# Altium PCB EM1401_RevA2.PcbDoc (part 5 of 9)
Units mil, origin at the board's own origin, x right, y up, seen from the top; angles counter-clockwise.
Board outline 7800 x 5300 mil, 6 copper layers (Top Layer, MidLayer1, MidLayer2, MidLayer3, MidLayer4, Bottom Layer), stack 16.8 mil thick; 751 components, 531 nets, 2554 pads, 1388 vias.
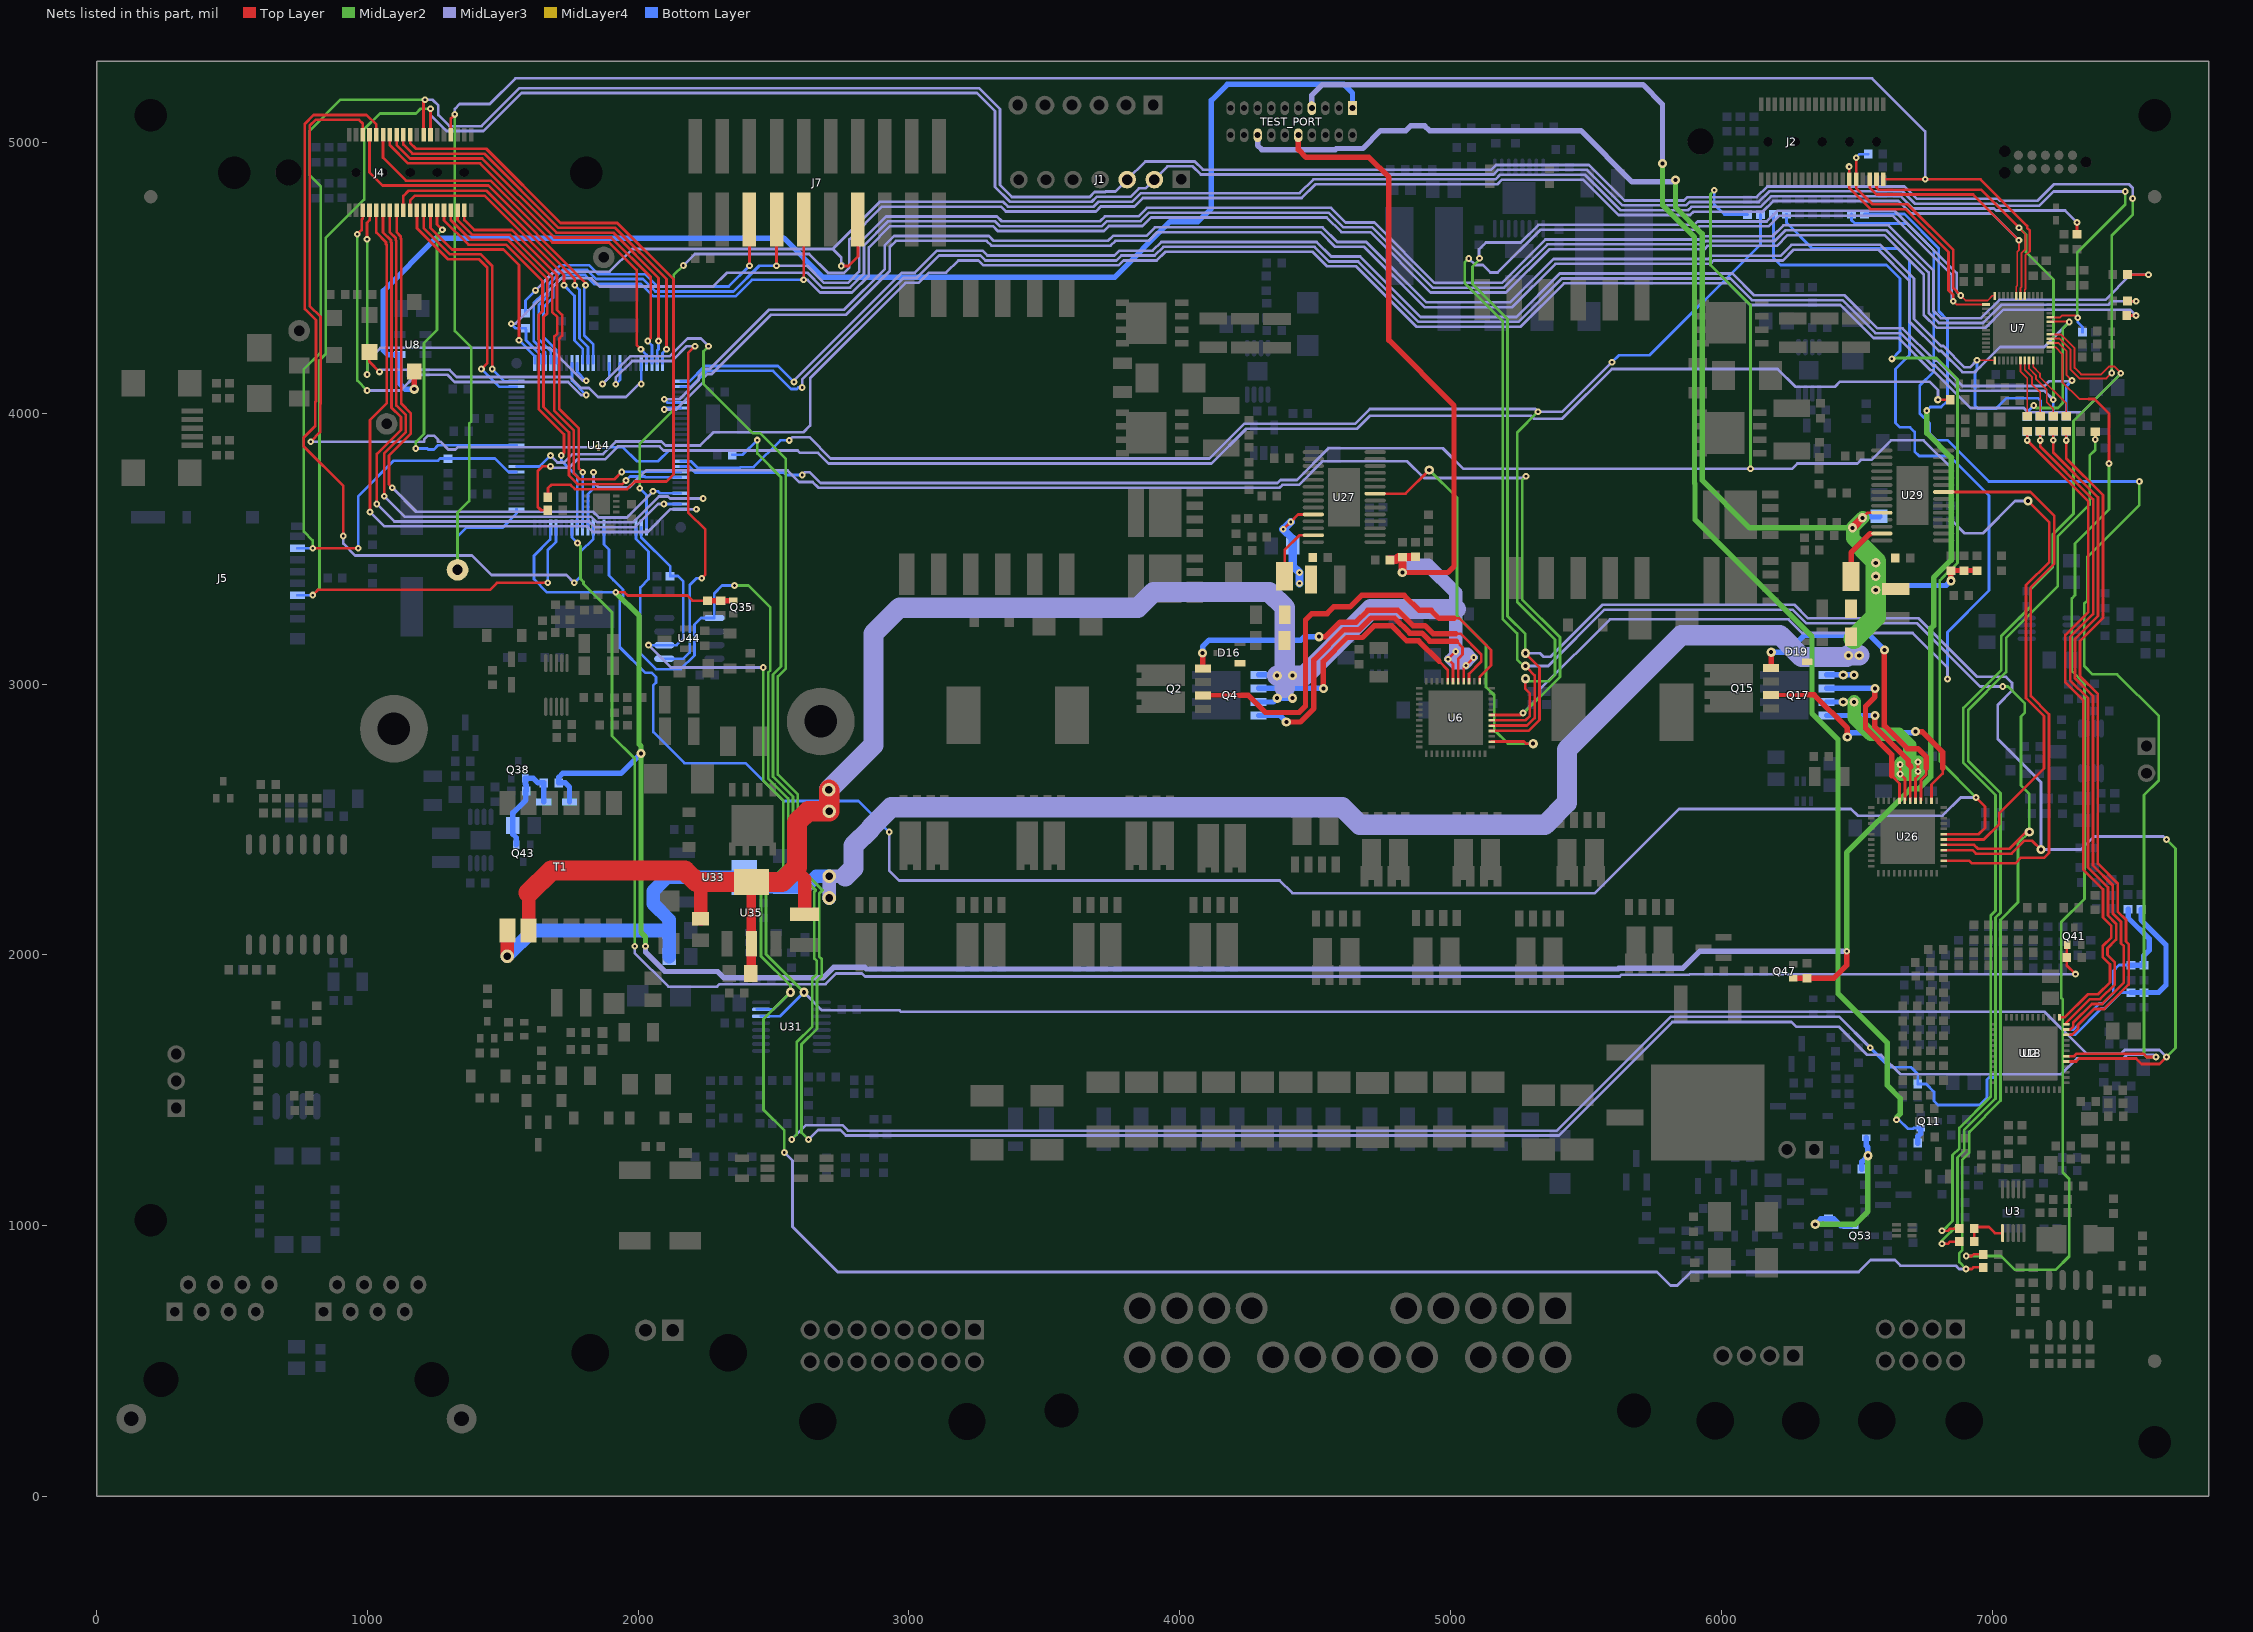
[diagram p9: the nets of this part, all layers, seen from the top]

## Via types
v1: diameter 25, hole 10, Top Layer to Bottom Layer, tented both sides, 275 vias
v2: diameter 16, hole 8, Top Layer to Bottom Layer, tented both sides, 240 vias
v3: diameter 34, hole 15, Top Layer to Bottom Layer, tented both sides, 158 vias
v4: diameter 34, hole 15, Top Layer to Bottom Layer, 154 vias
v5: diameter 34, hole 15, Top Layer to Bottom Layer, tented top, 95 vias
v6: diameter 34, hole 15, Top Layer to Bottom Layer, tented bottom, 89 vias
v7: diameter 25, hole 10, Top Layer to Bottom Layer, tented bottom, 75 vias
v8: diameter 25, hole 10, Top Layer to Bottom Layer, 62 vias
v9: diameter 28, hole 8, Top Layer to Bottom Layer, tented both sides, 60 vias
v10: diameter 24, hole 8, Top Layer to Bottom Layer, 53 vias
v11: diameter 25, hole 10, Top Layer to Bottom Layer, tented top, 28 vias
v12: diameter 50, hole 28, Top Layer to Bottom Layer, 28 vias
v13: diameter 25, hole 8, Top Layer to Bottom Layer, tented both sides, 18 vias
v14: diameter 50, hole 28, Top Layer to Bottom Layer, tented top, 12 vias
v15: diameter 25, hole 8, Top Layer to Bottom Layer, tented top, 9 vias
v16: diameter 20, hole 8, Top Layer to Bottom Layer, tented both sides, 9 vias
v17: diameter 24, hole 8, Top Layer to Bottom Layer, tented bottom, 4 vias
v18: diameter 24, hole 8, Top Layer to Bottom Layer, tented top, 4 vias
v19: diameter 28, hole 10, Top Layer to Bottom Layer, tented both sides, 3 vias
v20: diameter 35, hole 14, Top Layer to Bottom Layer, 3 vias
v21: diameter 50, hole 28, Top Layer to Bottom Layer, tented both sides, 2 vias
v22: diameter 50, hole 28, Top Layer to Bottom Layer, tented bottom, 2 vias
v23: diameter 30, hole 14, Top Layer to Bottom Layer, tented top, 2 vias
v24: diameter 28, hole 10, Top Layer to Bottom Layer, 1 vias
v25: diameter 35, hole 14, Top Layer to Bottom Layer, tented both sides, 1 vias
v26: diameter 35, hole 14, Top Layer to Bottom Layer, tented top, 1 vias

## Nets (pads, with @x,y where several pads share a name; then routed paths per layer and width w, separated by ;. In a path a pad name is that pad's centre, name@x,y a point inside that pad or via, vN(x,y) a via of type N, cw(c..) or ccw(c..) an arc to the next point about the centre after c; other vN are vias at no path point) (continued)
DOUT_LS: D56.1 Q53.2 R162.2 R263.1 | length 696.9
  MidLayer2 w20: v5(6347,1005) 6494,1005 6541.42,1052.42 v3(6541.42,1258.42)
  Bottom Layer w20: v5(6347,1005) 6367.56,1025.56 R263.1@6396,1025.56 6415.44,1025.56 6441,1000 Q53.2@6478,1000 ; R162.2@6518.98,1209 6518.98,1235.97 v3(6541.42,1258.42) 6541,1258.83 6541,1290 6535.42,1295.58 D56.1@6535.42,1324
EN_BOT: U6.26 U27.8 | length 1616.4
  Top Layer w10: U27.8@4721.62,3703.33 4833.74,3703.33 v5(4921.42,3791) ; U6.26@5152.77,2787.66 5271.09,2787.66 5278.75,2780 v4(5305.42,2780)
  MidLayer2 w10: v5(4921.42,3791) 5024,3688.42 5024,3252.33 5131.42,3144.91 5131.42,2988.75 5161.42,2958.75 5161.42,2831.04 5212.46,2780 v4(5305.42,2780)
EN_CEXT_BYPASS_: Q11.1 R24.1 TEST_PORT.7 | length 5673.1
  MidLayer2 w20: v4(5783,4923) 5783,4768.6 5901,4650.6 5901,3741.4 5903,3739.4 5903,3607 6335,3175 6335,2892 6431,2796 6431,1857 6613,1675 6613,1518 6660.5,1470.5 6660.5,1412.37 6647,1398.87 v1(6647,1391)
  MidLayer3 w20: TEST_PORT.7@4488,5127 4488,5175 4527,5214 5710,5214 5783,5141 v4(5783,4923) v4@5782,4922
  Bottom Layer w10: v1(6647,1391) 6656,1391 6689,1358 6707.48,1358 6709.89,1360.41 Q11.1@6736.01,1360.41
  Bottom Layer w20: R24.1@6726,1305 6726,1330 6736,1340 Q11.1@6736.01,1360.41
EN_CHECKSUM_: Q41.1 R137.2 U14.43 | length 7191
  Top Layer w10: Q41.1@7277.83,2037.01 7275.86,2035.04 R137.2@7275.86,1991 7275.86,1961.14 v1(7308,1929)
  MidLayer2 w10: v1(1776,3521) 1787,3510 1787,3389 1798.5,3377.5 1798.5,3370.44 1903.5,3265.44 1903.5,2808.49 1987.42,2724.57 v7@1987.42,2032
  MidLayer3 w10: v7(1987,2032) 1987,2007 2111.5,1882.5 2291.56,1882.5 2301.06,1892 2692,1892 2731,1931 2827,1931 2838,1920 5624.47,1920 5631.47,1927 5882,1927 5884,1929 v1(7308,1929)
  Bottom Layer w10: U14.43@1755.57,3578.85 1755.57,3541.43 v1(1776,3521)
EN_SW_: C104.2 D21.1 Q35.1 Q47.1 R87.2 R138.2 R169.1 R244.1 U14.47 | length 10817.1
  Top Layer w10: v1(1917,3339) 1949.94,3339 1961.44,3327.5 2181.5,3327.5 2201,3308 C104.2@2256,3308
  Top Layer w20: C104.2@2256,3308 2304.44,3308 R244.1@2305,3308.56 Q35.1@2350.5,3308.59 ; Q47.1@6265.91,1914.41 6316.01,1914.41 R169.1@6316.42,1914 6416,1914 6463,1961 v1(6463,2013)
  MidLayer2 w20: v1(1917,3339) 2003,3253 2003,2778 2010.42,2770.58 v4(2010.42,2744) 2010.42,2082.58 2027,2066 v7(2027,2032) ; v1(6463,2013) 6463,2378 6698,2613 6729,2613 6774,2658 6774,3206 6784,3216 6784,3393 6849,3458 6849,3837 6759,3927 v8(6759,4010)
  MidLayer3 w20: v7(2027,2032) 2027,2010 2098.5,1938.5 2293.63,1938.5 2317.13,1915 2682.47,1915 2721.47,1954 2836.53,1954 2842.53,1948 5619.95,1948 5621.95,1950 5857,1950 5920,2013 v1(6463,2013)
  Bottom Layer w10: U14.47@1676.83,3578.85 1675.15,3577.17 1675.15,3534.15 1615,3474 1615,3387.54 1663.54,3339 v1(1917,3339) ; R87.2@6529,4735.88 6676.12,4735.88 6803,4609 6803,4377 6835,4345 6835,4046 6812,4023 6772,4023 v8(6759,4010)
  Bottom Layer w20: D21.1@1746.49,2565 1746.49,2619.51 1731,2635 R138.2@1707,2635 1707,2656 1721,2670 1936.42,2670 v4(2010.42,2744)
EN_TOP: U26.26 U29.8 | length 2162.2
  Top Layer w10: U29.8@6821.05,3709.47 7141.95,3709.47 7229.42,3622.01 7229.42,3444.09 7143.14,3357.81 7143.14,2955.72 7210.42,2888.44 7210.42,2376.57 7192.84,2359 7107.37,2359 7086.37,2338 6925.5,2338 6916.09,2347.42 U26.26@6821.77,2347.42
EPIOS0/A0/D0: J4.5 U14.83 | length 1691.4
  Top Layer w10: v11(963,4661) 979,4677 979,4715 983,4719 J4.5@983,4750
  MidLayer2 w10: v11(963,4661) 963,4120.5 v1(999,4084.5)
  MidLayer3 w10: v1(999,4084.5) 1122.5,4084.5 1180.5,4142.5 1295.86,4142.5 1322.36,4116 1741.53,4116 1789.53,4068 v7(1808,4068)
  Bottom Layer w10: U14.83@1755.57,4185.15 1755.57,4120.43 v7(1808,4068)
EPIOS1/A1/D1: J4.7 U14.84 | length 1620.1
  Top Layer w10: v8(998.5,4643) 998.5,4703.5 1008.5,4713.5 1008.5,4749.5 J4.7@1008,4750
  MidLayer2 w10: v8(998.5,4643) 999,4642.5 v1(999,4143)
  MidLayer3 w10: v1(999,4143) 999,4193 1048,4242 1674,4242 1796,4120 v7(1808,4120)
  Bottom Layer w10: U14.84@1775.26,4185.15 1775.26,4152.74 v7(1808,4120)
EPIOS2/A2/D2: J4.9 U14.25 | length 2484.9
  Top Layer w10: v7(1009.5,3635.5) 1009.5,3975.5 1071,4037 1071,4622.18 1069,4624.18 1069,4631.63 1033,4667.63 J4.9@1033,4750
  MidLayer3 w10: v7(1009.5,3635.5) 1062.5,3582.5 1811.46,3582.5 1832.52,3561.44 2035.44,3561.44 2120,3646 v1(2215,3646)
  Bottom Layer w10: U14.25@2157.15,3645.78 2214.78,3645.78 v1(2215,3646)
EPIOS3/A3/D3: J4.11 U14.24 | length 2342.4
  Top Layer w10: v7(1035,3665) 1035,3849.94 1124,3938.94 1124,3985.6 1089,4020.6 1089,4629.63 1087,4631.63 1087,4639.09 1058,4668.09 J4.11@1058,4750
  MidLayer3 w10: v7(1035,3665) 1099.5,3600.5 1818.92,3600.5 1839.98,3579.44 1988.44,3579.44 2074,3665 v1(2095,3665)
  Bottom Layer w10: v1(2095,3665) 2156.68,3665 U14.24@2157.15,3665.46
EPIOS4/A4/D4: J4.13 U14.23 | length 2457
  Top Layer w10: v7(1062,3694) 1062,3851.48 1142,3931.48 1142,3993.06 1107,4028.06 1107,4637.09 1105,4639.09 1105,4646.54 1083,4668.54 J4.13@1083,4750
  MidLayer3 w10: v7(1062,3694) 1137.5,3618.5 1826.37,3618.5 1847.43,3597.44 1980.99,3597.44 2076.54,3693 2110,3693 2117.85,3685.15 v1(2239.85,3685.15)
  Bottom Layer w10: U14.23@2157.15,3685.15 v1(2239.85,3685.15)
EPIOS5/A5/D5: J4.15 U14.22 | length 2238.1
  Top Layer w10: v7(1092,3725) 1080,3737 1080,3844.03 1160,3924.03 1160,4000.51 1125,4035.51 1125,4644.54 1123,4646.54 1123,4654 1108,4669 J4.15@1108,4750
  MidLayer3 w10: v7(1092,3725) 1180.5,3636.5 1833.83,3636.5 1854.89,3615.44 1958.44,3615.44 v1(2055,3712)
  Bottom Layer w10: v1(2055,3712) 2074,3712 2081.17,3704.83 U14.22@2157.15,3704.83
EPIOS6/A6/D6: J4.17 U14.86 | length 1159.9
  Top Layer w10: J4.17@1133,4750 1133,4802.46 1152.54,4822 1440.54,4822 1766,4496.54 v1(1766,4473)
  Bottom Layer w10: v1(1766,4473) 1783,4456 1783,4276 1814.63,4244.37 U14.86@1814.63,4185.15
EPIOS7/A7/D7: J4.19 U14.85 | length 1087.7
  Top Layer w10: J4.19@1158,4750 1158,4786 1176,4804 1433.09,4804 1726,4511.09 v1(1726,4473)
  Bottom Layer w10: v1@1726.46,4473 v1(1726,4473) 1765,4434 1765,4268.54 1794.94,4238.6 U14.85@1794.94,4185.15
EPIOS8/A8/D8: J4.21 U14.74 | length 926.6
  Top Layer w10: J4.21@1183,4750 1183,4683.54 1297.54,4569 1411.54,4569 1443,4537.54 1443,4186 v7(1421,4164)
  Bottom Layer w10: v7(1421,4164) 1486.46,4098.54 U14.74@1550.85,4098.54
EPIOS9/A9/D9: J4.23 U14.75 | length 866.4
  Top Layer w10: J4.23@1208,4750 1208,4684 1305,4587 1419,4587 1461,4545 v7(1461,4164)
  Bottom Layer w10: v7(1461,4164) 1506.78,4118.22 U14.75@1550.85,4118.22
EPIOS10/A10/D10: J4.25 U14.76 | length 835.5
  Top Layer w10: J4.25@1233,4750 1233,4685 1313,4605 1503,4605 1560,4548 v8(1560,4270)
  Bottom Layer w10: v8(1560,4270) 1617.78,4212.22 U14.76@1617.78,4185.15
EPIOS11/A11/D11: J4.27 U14.63 | length 1309
  Top Layer w10: J4.27@1258,4750 1257,4749 1257,4698 v8(1277,4678)
  MidLayer2 w10: v7(1179,3870) 1179,3894 1209,3924 1209,4260 1257,4308 1257,4658 v8(1277,4678)
  Bottom Layer w10: v7(1179,3870) 1220.94,3870 1224.44,3866.5 1245.56,3866.5 1261.06,3882 U14.63@1550.85,3882
EPIOS12/A12/D12: J4.29 U14.42 | length 1476.7
  Top Layer w10: J4.29@1283,4750 1283,4712.63 1372.63,4623 1511.63,4623 1646.5,4488.13 1646.5,4377.02 1632.5,4363.02 1632.5,4016.13 1726.39,3922.25 1726.39,3854.39 v7(1716,3844)
  Bottom Layer w10: v7(1716,3844) 1716,3824.94 1775.26,3765.68 U14.42@1775.26,3578.85
EPIOS13/A13/D13: J4.31 U14.19 | length 1692.2
  Top Layer w10: J4.31@1308,4750 1308,4713.09 1380.09,4641 1519.09,4641 1664.5,4495.59 1664.5,4369.56 1650.5,4355.56 1650.5,4023.59 1744.39,3929.7 1744.39,3770.16 1776.04,3738.5 1941.5,3738.5 v1(1955,3752)
  Bottom Layer w10: v1(1955,3752) 1969.5,3766.5 2024.02,3766.5 2026.63,3763.89 U14.19@2157.15,3763.89
EPIOS14/A14/D14: J4.33 U14.18 | length 1660.3
  Top Layer w10: J4.33@1333,4750 1333,4713.54 1387.54,4659 1526.54,4659 1682.5,4503.04 1682.5,4374.56 1701.5,4355.56 1701.5,4294.44 1690.5,4283.44 1690.5,4009.04 1762.39,3937.16 1762.39,3777.61 1783.5,3756.5 1911.93,3756.5 v1(1939,3783.57)
  Bottom Layer w10: v1@1935,3783.57 1935.93,3784.5 2156.22,3784.5 U14.18@2157.15,3783.57
EPIOS15/A15/D15: J4.35 U14.41 | length 1442.7
  Top Layer w10: J4.35@1358,4750 1358,4714 1395,4677 1534,4677 1700.5,4510.5 1700.5,4382.02 1719.5,4363.02 1719.5,4286.98 1708.5,4275.98 1708.5,4016.5 1781,3944 1781,3796 v1(1795,3782)
  Bottom Layer w10: U14.41@1794.94,3578.85 1795,3578.91 v1(1795,3782)
EPIOS16/DQML: J4.6 U14.14 | length 2896.8
  Top Layer w10: v8@791,3896 825.5,3930.5 825.5,4034.56 828,4037.06 828,4355 787,4396 787,5062 809,5084 969,5084 983,5070 J4.6@983,5028
  MidLayer3 w10: v8@791,3895.5 1209.5,3895.5 1209.5,3902.56 1224.44,3917.5 1245.56,3917.5 1260.5,3902.56 1260.5,3895.5 1269.56,3895.5 1298.56,3866.5 1325.56,3866.5 1333.56,3874.5 v7(1853.5,3874.5)
  Bottom Layer w10: v7(1853.5,3874.5) 1944.56,3874.5 1996.06,3823 2074,3823 2113.32,3862.31 U14.14@2157.15,3862.31
  other v8: 791,3895
EPIOS17/DQMH: J4.8 U14.87 | length 1425.5
  Top Layer w10: J4.8@1008,5028 1008,4889 1056,4841 1447,4841 1806,4482 v1(1806,4473)
  Bottom Layer w10: v1@1809,4479 1806,4476 v1(1806,4473) 1801,4468 1801,4288 1834.32,4254.69 U14.87@1834.32,4185.15
EPIOS18/CASN: J4.10 U14.39 | length 3124
  Top Layer w10: v8(911,3547) 911,3731 765,3877 765,3910 807.5,3952.5 807.5,4042.5 810,4045 810,4344 769,4385 769,5069.46 801.54,5102 997,5102 1033,5066 J4.10@1033,5028
  MidLayer3 w10: v8(911,3547) 911,3519 955,3475 1386,3475 1458.21,3402.79 1735.21,3402.79 v1(1764,3374)
  Bottom Layer w10: v1(1764,3374) 1787.5,3397.5 1787.5,3489.41 1834.32,3536.23 U14.39@1834.32,3578.85
EPIOS19/RASN: J4.12 U14.97 | length 1551.7
  Top Layer w10: J4.12@1058,5028 1058,4944 1143,4859 1455.18,4859 1683.18,4631 1893,4631 1994.5,4529.5 1994.5,4252.5 v7(2010,4237)
  Bottom Layer w10: v7(2010,4237) 2031.17,4215.83 U14.97@2031.17,4185.15
EPIOS28/WEN: J4.14 U14.98 | length 1532.8
  Top Layer w10: J4.14@1083,5028 1083,4990 1150,4923 1416.63,4923 1690.63,4649 1900.46,4649 2047,4502.46 2047,4279 v7(2035,4267)
  Bottom Layer w10: v7(2035,4267) 2050.85,4251.15 U14.98@2050.85,4185.15
EPIOS29/CSN: J4.16 U14.99 | length 1524
  Top Layer w10: J4.16@1108,5028 1108,4991 1158,4941 1424.09,4941 1698.09,4667 1907.91,4667 2075,4499.91 v7(2075,4267)
  Bottom Layer w10: U14.99@2070.54,4185.15 2070.54,4232.54 2075,4237 v7(2075,4267)
EPIOS30/CKE: J4.18 U14.100 | length 1529.5
  Top Layer w10: J4.18@1133,5028 1133,4993 1167,4959 1431.54,4959 1705.54,4685 1915.37,4685 2105,4495.37 v7(2105,4237)
  Bottom Layer w10: U14.100@2090.22,4185.15 2090.22,4222.22 v7(2105,4237)
EPIOS31/CLK: J4.20 R286.1 | length 2462.7
  Top Layer w10: J4.20@1158,5028 1158,4999 1180,4977 1439,4977 1713,4703 1922.82,4703 2130.5,4495.32 2130.5,3774.5 2104.5,3748.5 1987.56,3748.5 1959.06,3720 1766,3720 1750,3736 1679,3736 1666.88,3723.88 R286.1@1666.88,3690
FAULT_INT_BOT_: R267.2 U6.31 U14.40 | length 9181.8
  Top Layer w10: U6.31@5152.77,2886.09 5259.5,2886.09 v1@5267.42,2894
  MidLayer2 w10: v1(5267.42,2893) 5270.46,2893 5404,3026.54 5404,3173 5264.42,3312.58 5264.42,3753.42 v11(5279,3768)
  MidLayer3 w10: v1(1835,3782) 1835,3746 1854.5,3726.5 1965.56,3726.5 1966.06,3727 1967,3727 2029.5,3789.5 2551.5,3789.5 2594.5,3746.5 2644.22,3746.5 2665.72,3725 4368.3,3725 4379.3,3736 4441,3736 4528,3823 4840,3823 4902,3761 5272,3761 v11(5279,3768) ; v1(5267.42,2893) 5331,2956.58 5331,2981.54 5588.46,3239 6248.54,3239 6298.54,3189 6706.84,3189 6835,3060.84 v8(6835,3019)
  Bottom Layer w10: U14.40@1814.63,3578.85 1814.63,3701.63 1835,3722 v1(1835,3782) ; R267.2@6241,4734.88 6241,4704 6336,4609 6650.27,4609 6695,4564.27 6695,4215.46 6643,4163.46 6643,3965 6660,3948 6697,3948 6714,3931 6714,3859 6731,3842 6843,3842 6988.92,3696.08 6988.92,3345.37 6835,3191.46 v8(6835,3019)
FAULT_INT_TOP_: R258.2 U14.37 U26.31 | length 9401.1
  Top Layer w10: U26.31@6821.77,2445.84 6822.12,2445.5 6920.56,2445.5 6920.9,2445.84 6929.1,2445.84 6929.44,2445.5 6950.56,2445.5 6974,2468.94 6974,2548 v7(6941,2581)
  MidLayer2 w10: v8@6633,4204 6794,4204 6872,4126 6872,3448 6835.5,3411.5 6817.92,3393.93 ; 6817.92,3393.92 6807,3383 6807,2715 v7(6941,2581)
  MidLayer3 w10: v8(2927,2454) 2927,2311 2963,2275 4369,2275 4416,2228 5533,2228 5844,2539 6479,2539 6504,2514 6817.35,2514 6884.35,2581 v7(6941,2581)
  Bottom Layer w10: U14.37@1873.68,3578.85 1873.68,3515.31 1892,3497 1892,3400.94 1908.44,3384.5 1908.5,3384.5 1944,3349 1944,3323 1932,3311 1932,3136 2026.5,3041.5 2050.56,3041.5 2065.5,3026.56 2065.5,3005.44 2056,2995.94 2056,2823 2171,2708 2397,2708 2537,2568 2813,2568 v8(2927,2454) ; R258.2@6193,4734.88 6193,4574 6219,4548 6610,4548 6660,4498 6660,4231 v8(6630,4201)
FPGA_CLK_: R85.2 R88.1 | length 5695.8
  Top Layer w10: R88.1@1666.88,3642 1642,3642 1629,3655 1629,3786 1647,3804 v7(1676,3804) ; v24(6800,4050) R85.2@6844.88,4050
  MidLayer3 w10: v7(1676,3804) 1681,3799 1744,3799 1775,3830 1877,3830 1925,3878 2079,3878 2094,3863 2588.94,3863 2597.94,3854 2664,3854 2703,3815 4117.62,3815 4245.62,3943 4655,3943 4703,3991 5297,3991 5308,3980 5412.46,3980 5595.96,4163.5 6208.04,4163.5 6273.54,4098 6419.57,4098 6438.57,4117 6769,4117 6800,4086 v24(6800,4050)
FPGA_MUX0: R92.1 U7.7 | length 206.8
  Top Layer w7: U7.7@7104.87,4195.91 7104.87,4155.27 7130,4130.15 R92.1@7130,3999.56
FPGA_MUX1: R97.1 U7.8 | length 231.1
  Top Layer w7: U7.8@7120.62,4195.91 7120.62,4160.74 7147,4134.36 7147,4108 7178,4077 R97.1@7178,3988.56
FPGA_MUX2: R99.1 U7.9 | length 244.5
  Top Layer w7: U7.9@7136.37,4195.91 7136.37,4166.2 7162,4140.57 7162,4127.85 7202,4087.85 7202,4040 7226,4016 R99.1@7226,3988.56
FPGA_MUX3: R101.1 U7.10 | length 257.8
  Top Layer w7: U7.10@7152.12,4195.91 7152.12,4171.67 7177,4146.79 7177,4134.06 7274,4037.06 R101.1@7274,3988.56
GATE_8B: Q4.2 U6.44 | length 962.7
  Top Layer w10: 4957.42,3085 4989.39,3053.03 U6.44@4989.39,3010.1
  Top Layer w20: v4(4530.42,2984) 4530.42,3084 4618.42,3172 4674.42,3172 4718.42,3216 4782.43,3216 4838.43,3160 4882.42,3160 4957.42,3085
  Bottom Layer w20: Q4.2@4291.75,2984 v4(4530.42,2984)
GATE_8T: Q17.2 U26.44 | length 659.5
  Top Layer w10: 6629.42,2662 6658.39,2633.03 U26.44@6658.39,2569.86
  Top Layer w20: v4(6567.42,2984) 6567.42,2953 6532.42,2918 6532.42,2837 6629.42,2740 6629.42,2662
  Bottom Layer w20: Q17.2@6388.75,2984 v4(6567.42,2984)
GATE_9B: Q4.4 U6.42 | length 1204
  Top Layer w10: 5022.06,3158.35 5044.5,3135.92 5044.5,3109.36 5028.76,3093.62 U6.42@5028.76,3010.1
  Top Layer w20: v4(4393.75,2860) 4445.42,2860 4495.42,2910 4495.42,3089.44 4606.98,3201 4663.42,3201 4706.42,3244 4794.02,3244 4850.02,3188 4894.01,3188 4923.66,3158.35 5022.06,3158.35
  Bottom Layer w20: Q4.4@4291.75,2884 4369.75,2884 v4(4393.75,2860)
GATE_9T: Q17.4 U26.42 | length 549
  Top Layer w10: U26.42@6697.76,2569.86 6697.76,2692.34 6700.42,2695
  Top Layer w20: v4(6567.42,2884) 6567.42,2841.6 6690.92,2718.1 6690.92,2704.5 6700.42,2695
  Bottom Layer w20: Q17.4@6388.75,2884 v4(6567.42,2884)
GATE_10B: Q2.4 U6.40 | length 1351.8
  Top Layer w10: 5020.42,3186.35 5037.06,3186.35 5113.42,3110 5113.42,3083.37 5068.13,3038.08 U6.40@5068.13,3010.1
  Top Layer w20: v5(4084.42,3115) 4084.42,3059.33 Q2.4@4085.75,3058 ; v4(4514.42,3175) 4538.42,3175 4592.42,3229 4651.82,3229 4694.82,3272 4805.62,3272 4861.62,3216 4905.61,3216 4935.26,3186.35 5020.42,3186.35
  Bottom Layer w20: v5@4084.42,3114 v5(4084.42,3115) 4084.42,3138 4108.42,3162 4447,3162 4460,3175 v4(4514.42,3175)
GATE_10T: Q15.4 U26.40 | length 1176.3
  Top Layer w10: U26.40@6737.13,2569.86 6737.13,2645.71 6757.42,2666 6757.42,2689
  Top Layer w20: Q15.4@6184.27,3059.24 6184.27,3117.71 v5@6184.42,3117.86 ; v4(6602.42,3126) 6602.42,2846.4 6687.32,2761.5 6725.92,2761.5 6757.42,2730 6757.42,2689
  Bottom Layer w20: v5(6184.27,3117.86) 6243.67,3117.86 6305.82,3180 6548.42,3180 v4(6602.42,3126)
GATE_11B: Q2.2 U6.38 | length 1673
  Top Layer w10: 5014.42,3243 5032.42,3243 5149.42,3126 5149.42,3068.46 5107.5,3026.54 U6.38@5107.5,3010.1
  Top Layer w16: Q2.2@4085.75,2959 4222.42,2959
  Top Layer w20: 4222.42,2959 4252.42,2959 4316.42,2895 4440.82,2895 4464.42,2918.6 4464.42,3237 4487.92,3260.5 4544.12,3260.5 4568.62,3285 4628.62,3285 4671.62,3328 4828.82,3328 4884.82,3272 4928.81,3272 4957.81,3243 5014.42,3243
GATE_11T: Q15.2 U26.38 | length 952
  Top Layer w10: U26.38@6776.5,2569.86 6776.5,2629.08 6817.42,2670 6817.42,2689
  Top Layer w16: Q15.2@6184.27,2959.24 6184.87,2959.83 6321.17,2959.83
  Top Layer w20: 6321.17,2959.9 6342.52,2959.9 6465.42,2837 v4(6465.42,2805) ; v4(6716.79,2824.62) 6741.99,2824.62 6817.42,2749.2 6817.42,2689
  Bottom Layer w20: v4(6465.42,2805) 6480.42,2820 6712.17,2820 v4(6716.79,2824.62)
GNDF1: C121.2 C126.2 C127.2 C164.2 C165.2 C215.1 C217.2 C219.2 C232.1 D16.1 Q4.1 Q4.3 R174.2 R220.1 R236.2 T1.8 TEST_PORT.10 U6.41 U6.43 U27.24 U27.27 U35.2 U35.4 | length 9866.2
  Top Layer w10: v11(4382,3572) 4383,3572 v11(4410,3599) 4437.56,3626.56 U27.24@4493.28,3626.56 ; R174.2@4387.4,3398 4387.4,3495.4 4441.78,3549.78 U27.27@4493.28,3549.78 ; U6.43@5009.07,3010.1 5009.07,3073.93 v1(4991,3092) v1(5019,3120) ; U6.41@5048.44,3010.1 5048.44,3060.44 v1(5057,3069) v1(5086,3098)
  Top Layer w20: TEST_PORT.10@4438,5028 TEST_PORT.10@4438,5027 4438,4974 4467,4945 4699,4945 4772,4872 4772,4270 5013,4029 5013,3435 4990,3412 v4(4822,3412)
  Top Layer w30: C232.1@4776.53,3459 4798,3459 4807.88,3468.88 C217.2@4822.42,3468.88 ; v4(4822,3412) 4822.42,3412.42 C217.2@4822.42,3468.88 ; R236.2@4870.42,3469.44 4822.98,3469.44 C217.2@4822.42,3468.88
  Top Layer w35: R220.1@2416.42,1932 2418.42,1934 U35.2@2418.42,2040.83 U35.4@2418.42,2269.17
  Top Layer w50: T1.8@1595.89,2090.76 1595.89,2228.89 ; 2215.24,2269.17 2230.42,2254 C164.2@2230.42,2134 ; 2573.42,2321 2578.37,2316.04 2615.42,2279 C165.2@2615.42,2150.24
  Top Layer w75: 1595.89,2228.89 1678.5,2311.5 2172.92,2311.5 2215.24,2269.17 U35.4@2418.42,2269.17 2531.51,2269.17 2578.37,2316.04 2586.42,2324.08 2586.42,2489 2627.42,2530 v12(2705.42,2530) 2705.42,2609 v12(2704.42,2610)
  MidLayer3 w30: v4(4822,3412) 4848,3438 ; v1@4997,3098 v1(5086,3098) ; v1@4997,3098 v1(5019,3120) 5064,3120 v1(5086,3098) ; v1@4997,3098 v1(4991,3092) 5014,3069 v1(5057,3069) v1(5086,3098)
  MidLayer3 w50: v12(2704.42,2610) 2705.42,2609 v12(2705.42,2530) ; 4848,3438 4918,3438 5019,3337 5019,3277 v1(5019,3120)
  MidLayer3 w75: v12(2704.42,2610) 2869,2774.58 2869,3186 2965,3282 3845,3282 3903,3340 4331,3340 4388,3283 4388,3031 ; v5(4360,3031) 4388,3031 ; 4388,2987 4388,3031 ; 5019,3277 4705,3277 4459,3031 4388,3031
  MidLayer4 w50: v12(2704.42,2610) v12@2705.42,2609
  Bottom Layer w20: Q4.3@4291.75,2934 4346,2934 v5(4360,2948) v5(4417,2948) ; Q4.1@4291.75,3034 4357,3034 v5(4360,3031) 4416,3031 v5(4417,3032)
  Bottom Layer w30: v11(4410,3599) 4383,3572 v11(4382,3572) 4417.42,3536.58 C219.2@4417.42,3510 4417.42,3436.58 v1(4442,3412) v1(4442,3372)
GNDF2: C131.2 C136.2 C137.2 C158.2 C159.2 C216.1 C218.2 C221.2 C234.1 D19.1 Q17.1 Q17.3 R192.2 R214.1 R239.2 T1.7 TEST_PORT.16 U26.41 U26.43 U29.24 U29.27 U33.2 U33.4 | length 12290.8
  Top Layer w10: v3(6521.84,3614.15) 6540.4,3632.7 U29.24@6592.7,3632.7 ; 6549.35,3555.93 U29.27@6592.7,3555.93 ; v1(6660.42,2703) v1(6660.42,2668) 6678.07,2650.34 U26.43@6678.07,2569.86 ; U26.41@6717.44,2569.86 6717.44,2652.03 6726.42,2661 v1(6726.42,2677) v1(6726.42,2712)
  Top Layer w20: R192.2@6479.4,3411 6479.4,3485.99 6549.35,3555.93 ; v5(6847.92,3381.5) C234.1@6847.92,3419.44 C218.2@6895.92,3419.44 R239.2@6943.92,3419.44
  Top Layer w30: v5(6484.84,3577.15) v3(6521.84,3614.15)
  Top Layer w50: v12(1517,1995) 1517,2090.61 T1.7@1517.15,2090.76
  MidLayer2 w20: v4(5831,4862) 5831,4761 5929,4663 5929,3753 6104.85,3577.15 v5(6484.84,3577.15)
  MidLayer2 w50: v3(6490.42,2934) 6490.42,2876 6551.42,2815 6655.71,2815 6696.42,2774.29 6696.42,2712 ; 6521.84,3502.43 6484.84,3539.43 v5(6484.84,3577.15) v3(6521.84,3614.15) ; 6696.42,2712 v1(6726.42,2712) v1(6726.42,2677) 6717.42,2668 v1(6660.42,2668) v1(6660.42,2703) 6669.42,2712 6696.42,2712
  MidLayer2 w75: 6489.42,3167 6570.42,3248 v5(6570.42,3348) v4(6570.42,3398) v4(6570.42,3448) 6570.42,3453.85 6521.84,3502.43
  MidLayer3 w20: TEST_PORT.16@4288,5027 4288,4989 4303,4974 4574.42,4974 4578.42,4978 4676,4978 4741.99,5043.99 4834.9,5043.99 4852.5,5061.6 4904.69,5061.6 4922.3,5043.99 5482.01,5043.99 5671,4855 5824,4855 v4(5831,4862)
  MidLayer3 w50: v14(2706.42,2210) 2706.42,2289 v14(2705.42,2290) 2765,2290
  MidLayer3 w75: 2765,2290 2795,2320 2795,2402.5 2858.92,2466.42 2858.92,2468.92 2935,2545 4600,2545 4665,2480 5349,2480 5430,2561 5430,2758 5852.36,3180.36 6216.85,3180.36 6297.2,3100 6463.42,3100 v3(6469.42,3106) v3(6509.42,3106)
  Bottom Layer w10: v1(6660.42,2668) v1(6660.42,2703) ; v1(6726.42,2677) v1(6726.42,2712)
  Bottom Layer w20: Q17.3@6388.75,2934 v3(6450.42,2934) v3(6490.42,2934) ; Q17.1@6388.75,3034 v3(6450.42,3034) v3(6490.42,3034) ; v4(6570.42,3398) 6604.42,3364 6830.42,3364 v5(6847.92,3381.5)
  Bottom Layer w25: v3(6521.84,3614.15) 6527.69,3620 C221.2@6582.42,3620
  Bottom Layer w50: v12(1517,1995) 1612,2090 R214.1@2114.42,2090 ; C158.2@2114.42,1994 R214.1@2114.42,2090 ; U33.4@2391.76,2283 2449.42,2283 2481.5,2250.91 C159.2@2550.42,2250.91 2618.33,2250.91 2657.42,2290 v14(2705.42,2290) 2706.42,2289 v14(2706.42,2210) ; U33.4@2391.76,2286 U33.2@2163.42,2286 2106,2286 2055,2235 2055,2189.39 2114.42,2129.98 R214.1@2114.42,2090
GREEN: D46.2 U14.96 | length 1196.7
  Top Layer w10: D46.2@1007,4226 1007,4191 v7(1045,4153)
  MidLayer3 w10: v7(1045,4153) 1052.5,4160.5 1303.32,4160.5 1329.82,4134 1748.98,4134 1789.48,4093.5 1818.56,4093.5 1852.06,4060 1955.06,4060 2003.58,4108.52 v7(2011.48,4108.52)
  Bottom Layer w10: v7(2011.48,4108.52) U14.96@2011.48,4185.15
HEART_: R42.1 R56.1 U18.2 | length 7760.2
  MidLayer2 w10: v1(2440,3901) 2440,3851.46 2527.5,3763.96 2527.5,3064.98 2498,3035.48 2498,2658.37 2571.78,2584.59 2571.78,2322.59 2655.79,2238.57 2650.42,2233.2 2650.42,1986.32 2660,1976.74 2660,1929.5 2642.42,1911.91 2642.42,1734.37 2585.42,1677.37 2585.42,1336.42 v8(2567,1318)
  MidLayer3 w10: v8(2567,1318) 2620,1371 2754.3,1371 2774.3,1351 5392.63,1351 5813.63,1772 6435,1772 v1(6550,1657)
  Bottom Layer w10: R56.1@2347.12,3847 2386,3847 v1(2440,3901) ; v1(6550,1657) 6622.08,1584.92 6701.08,1584.92 6725,1561 R42.1@6725,1523 6757,1523 6785.8,1494.2 6785.8,1460.53 6800.83,1445.5 6954.04,1445.5 6981,1472.46 6981,1540 6988.34,1547.34 U18.2@7006.84,1547.34
HIB_: J2.37 J4.32 TP1.1 U7.29 U14.51 | length 8830.7
  Top Layer w7: U7.29@7120.62,4434.09 7120.62,4457.2 7123,4459.57 7123,4582.86 7139.5,4599.36
  Top Layer w10: J4.32@1308,5028 1308,5089 v8(1323,5104) ; J2.37@6598,4864 v1(6753,4864) 6958,4864 7129.5,4692.5 7129.5,4684.44 7139.5,4674.44 7139.5,4599.36
  MidLayer2 w10: v8(1323,5104) 1323,4304 1383.93,4243.07 1383.93,3969.86 1375.94,3961.88 1375.94,3675.94 1333,3633 TP1.1@1333,3422
  MidLayer3 w10: v8(1323,5104) 1323,5124 1341,5142 1451.92,5142 1546.92,5237 6557,5237 6753,5041 v1(6753,4864)
  Bottom Layer w10: TP1.1@1333,3422 1333,3545.54 1364.46,3577 1498,3577 1550.85,3629.85 U14.51@1550.85,3645.78
HTH: C77.1 R135.2 R136.1 U18.26 | length 680.7
  Bottom Layer w10: U18.26@7274.55,1724.51 7300.38,1724.51 7396.87,1821 7409.87,1821 7447.82,1858.95 7447.82,1941.4 7468.84,1962.43 C77.1@7512.42,1962.43
  Bottom Layer w20: R136.1@7502.42,2167.88 7502.42,2137.13 7579.92,2059.63 7579.92,2016.84 7560.42,1997.34 R135.2@7560.42,1961.12 ; C77.1@7512.42,1961.12 R135.2@7560.42,1961.12 ; R135.2@7560.42,1960.12 R135.2@7560.42,1961.12
HV_SD: C65.2 D21.2 Q38.1 Q43.1 R138.1 R250.2 | length 419.3
  Bottom Layer w20: Q43.1@1550.41,2406.5 1550.41,2432.59 1537,2446 1537,2524.5 1585,2572.5 R250.2@1585,2605.62 ; R250.2@1587.12,2605.5 1587,2605.62 1587,2627 1582.59,2631.41 Q38.1@1582.59,2652.01 1610.99,2652.01 1613,2652 1630,2635 R138.1@1651.88,2635 1652,2634.88 D21.2@1652,2565
JTAG_TDO: J7.13 R230.1 R245.2 | length 6445.6
  Top Layer w10: v8(2750,4544) 2777,4544 2812,4579 2812,4715 J7.13@2811,4716 ; R230.1@7314,4661.56 v1(7314,4705)
  MidLayer3 w10: v1(1621,4454) 1690,4523 1894.95,4523 1978.45,4606.5 2718.5,4606.5 ; v8@2757.5,4551.5 v8(2750,4544) 2750,4575 2718.5,4606.5 ; v1(7314,4705) 7313.94,4705 7271.5,4747.44 7271.5,4747.5 7270,4749 7014.46,4749 7007.46,4756 6708.01,4756 6662.01,4802 6184.91,4802 6145.29,4762.38 5889.77,4762.38 5877.39,4750 5627.51,4750 5496.51,4881 5182.54,4881 5165.54,4864 4494,4864 4443,4813 3856.46,4813 3824.98,4781.52 3700.89,4781.52 3682.56,4763.2 3365.12,4763.2 3347.12,4781.2 2893.09,4781.2 2718.5,4606.6 2718.5,4606.5
  Bottom Layer w10: R245.2@1584,4369.12 1584,4417 v1(1621,4454) v1@1622,4454
JTCK/SWCLK: J7.9 R231.1 U14.80 | length 7174.6
  Top Layer w10: v8(2611,4493) J7.9@2611,4716 ; R231.1@7497.56,4361 v1(7531.5,4361)
  MidLayer3 w10: v8(2611,4493) 2625.11,4493 2672.11,4446 2789.89,4446 2852,4508.11 2852,4612.82 2930.37,4691.2 3309.84,4691.2 3327.84,4673.2 3719.84,4673.2 3738.17,4691.52 3862.25,4691.52 3893.73,4723 4542.73,4723 4596.73,4669 4703.73,4669 4926.73,4446 5205.22,4446 5365.22,4606 5937.04,4606 5949.42,4618.38 6204.94,4618.38 6244.56,4658 6602.37,4658 6747.73,4512.64 6747.73,4363.84 6796.07,4315.5 6974.73,4315.5 7042.23,4383 7509.5,4383 v1(7531.5,4361)
  Bottom Layer w10: U14.80@1696.52,4185.15 1696.52,4235.3 1650.5,4281.32 1650.5,4391.59 1686,4427.09 1686,4469.06 1727.94,4511 1804.09,4511 1837.41,4477.68 2010.32,4477.68 2056,4432 2359.52,4432 2420.52,4493 v8(2611,4493)
JTDI/SWO: J7.5 U14.78 | length 1353.9
  Top Layer w10: v8(2411,4545) J7.5@2411,4716
  Bottom Layer w10: U14.78@1657.15,4185.15 1657.15,4223.76 1614.5,4266.41 1614.5,4406.5 1650,4442 1650,4483.97 1713.03,4547 1819,4547 1852.32,4513.68 2025.23,4513.68 2070.91,4468 2334,4468 v8(2411,4545)
JTDO/TRACESWO: R229.1 R245.1 U14.77 | length 7017.9
  Top Layer w10: R229.1@7500.12,4414 v1(7532,4414)
  MidLayer3 w10: v8(1531,4331) 1547.8,4331 1715.3,4498.5 1827.5,4498.5 1857.57,4468.43 2276.96,4468.43 2327.53,4519 2624.57,4519 2679.57,4464 2782.43,4464 2834,4515.57 2834,4620.28 2922.92,4709.2 3317.29,4709.2 3335.29,4691.2 3712.39,4691.2 3730.71,4709.52 3854.8,4709.52 3886.28,4741 4550.19,4741 4604.19,4687 4711.19,4687 4934.19,4464 5197.77,4464 5357.77,4624 5929.58,4624 5941.96,4636.38 6197.48,4636.38 6237.1,4676 6609.82,4676 6765.73,4520.1 6765.73,4371.3 6803.53,4333.5 6967.27,4333.5 7034.77,4401 7429.91,4401 7442.91,4414 v1(7532,4414)
  Bottom Layer w10: v8(1531,4331) 1548,4314 R245.1@1584,4314 ; R245.1@1585.56,4307.12 1585.56,4269.89 1637.46,4217.99 U14.77@1637.46,4185.15
JTMS/SWDIO: J7.7 R232.1 U14.79 | length 7292.3
  Top Layer w10: v8(2511,4545) J7.7@2511,4716 ; R232.1@7500.12,4512 v1(7578,4512)
  MidLayer3 w10: v8(2511,4545) 2624.03,4545 2687.03,4482 2774.97,4482 2816,4523.03 2816,4627.73 2915.46,4727.2 3324.75,4727.2 3342.75,4709.2 3704.93,4709.2 3723.25,4727.52 3847.34,4727.52 3878.82,4759 4558.57,4759 4612.57,4705 4718.65,4705 4941.65,4482 5190.31,4482 5350.31,4642 5922.13,4642 5934.51,4654.38 6190.03,4654.38 6229.65,4694 6617.28,4694 6783.73,4527.55 6783.73,4378.76 6810.98,4351.5 6959.82,4351.5 7027.32,4419 7419,4419 7512,4512 v1(7578,4512)
  Bottom Layer w10: U14.79@1676.83,4185.15 1676.83,4229.53 1632.5,4273.87 1632.5,4399.04 1668,4434.54 1668,4476.52 1720.48,4529 1811.54,4529 1844.87,4495.68 2017.78,4495.68 2063.46,4450 2352.06,4450 2447.06,4545 v8(2511,4545)
LTH: C74.1 R132.2 R133.1 U18.27 | length 761.7
  Bottom Layer w10: U18.27@7274.55,1704.82 7306.18,1704.82 7404.35,1803 7417.33,1803 7475.33,1861 R132.2@7512.42,1861
  Bottom Layer w20: R132.2@7512.42,1861 C74.1@7560.42,1861 7615.42,1861 7642.42,1888 7642.42,2036.73 7550.42,2128.73 R133.1@7550.42,2167.88
MANUAL_RESET_: SW1.2 TEST_PORT.1 U8.4 | length 4841
  Top Layer w20: v4(1173,4089) SW1.2@1173,4155.05
  Bottom Layer w20: v4(1173,4089) 1139,4089 1119.76,4108.24 U8.4@1119.76,4216.6 1074.4,4216.6 1059,4232 1059,4452.13 1253.87,4647 2538,4647 2683,4502 3759.4,4502 3964.9,4707.5 4067.5,4707.5 4117,4757 4117,5156 4176,5215 4606,5215 4638,5183 TEST_PORT.1@4638,5127
MISO_1_: C49.2 J2.27 R155.2 U6.29 U7.37 U14.30 U26.29 U31.15 U44.2 | length 17621.1
  Top Layer w7: v1(6857,4414) 6869.39,4401.61 U7.37@6977.91,4401.61
  Top Layer w10: U6.29@5152.77,2846.72 5282.65,2846.72 5310.92,2874.98 5310.92,3032.5 5282.42,3061 v4@5276.42,3061 ; v1(6472,4911) 6472,4865 J2.27@6473,4864 6473,4831.54 6550.54,4754 6680.17,4754 6839,4595.17 6839,4454.54 6857,4436.54 v1(6857,4414) ; U26.29@6821.77,2406.47 6933.94,2406.47 6948.42,2392 7064,2392 7126,2454 v3(7137.42,2454) ; v1(6904.02,840) 6925.61,840 6931.61,846 R155.2@6967.88,846
  MidLayer2 w10: v11(2462,3061) 2462,2643.46 2535.78,2569.67 2535.78,2322.59 2454,2240.8 2454,1994.96 2562.42,1886.54 v3(2562.42,1862) 2463,1762.58 2463,1428 2540,1351 v8(2540,1270) ; v7(5067,4572) 5053,4558 5053,4480 5192.42,4340.58 5192.42,3241.21 5246,3187.62 5246,3091.42 v4@5276.42,3061 ; v1(6904.02,840) 6878.94,865.08 6878.94,898.56 6890,909.62 6890,1243.66 6916,1269.66 6916,1346.54 7031,1461.54 7031,2129.46 7096,2194.46 7096,2412.58 v3(7137.42,2454) 7137.42,2594.58 7106.44,2625.56 7106.44,2879.99 7121,2894.54 7121,2929 7059,2991 v7(7039.42,2991)
  MidLayer3 w10: v1(2038,3144) 2121,3061 v11(2462,3061) ; v8(2540,1270) 2570,1240 2570,996 2737,829 5762.57,829 5812.57,779 5837.43,779 5887.43,829 6507.12,829 6551.12,873 6640.88,873 6661.65,852.23 6865.75,852.23 6877.98,840 v1(6904.02,840) ; v3(2562.42,1862) v3@2569.99,1862 ; v7(5067,4572) 5091.5,4547.5 5119.5,4547.5 5147,4520 5173.92,4520 5331.92,4678 5907.21,4678 5919.6,4690.38 6175.12,4690.38 6214.73,4730 6632.19,4730 6851.38,4510.81 6851.38,4419.62 v1(6857,4414) ; v4(5276.42,3067) 5361,3067 5569,3275 6263.46,3275 6313.46,3225 6721.75,3225 6955.75,2991 v7(7039.42,2991)
  Bottom Layer w10: U14.30@2011.48,3578.85 2011.48,3541.89 2118,3435.37 C49.2@2118,3399 2147,3399 2167,3379 2167,3169 2142,3144 U44.2@2096.48,3144 v1(2038,3144) ; U31.15@2437.71,1798.98 U31.15@2453.71,1798.98 2499.39,1798.98 v3(2562.42,1862)
MISO_2_: C55.1 J1.3 J4.24 J5.7 U7.16 U14.58 | length 11280.6
  Top Layer w7: U7.16@7216.09,4275.63 7249.03,4275.63 7290,4234.66 7290,4161.79 7290.39,4161.39 7290.39,4160.61 7322,4129 7422,4129 v1(7442,4149)
  Top Layer w10: v7(798,3501.86) 798.14,3502 v7(966,3502) ; J4.24@1208,5028 1207.5,5028.5 1207.5,5148.5 v8@1213,5154
  MidLayer2 w10: v7(798,3501.86) 798,3531 765.5,3563.5 765.5,4163.04 828,4225.54 828,4837.94 787.5,4878.44 787.5,5044.5 901.44,5158.44 v8@1203.27,5158.44 ; v1(7442,4149) 7442,4656 7519,4733 v1(7519,4793)
  MidLayer3 w10: v8(1213,5158) 1240,5158 1262,5136 1262,5102 1303.58,5060.42 1421.25,5060.42 1561.83,5201 3258.46,5201 3336,5123.46 3336,4843.23 3380.03,4799.2 3667.65,4799.2 3685.98,4817.52 3686.87,4817.52 3687.02,4817.66 3687.16,4817.52 3724.84,4817.52 3726.34,4819.02 3762.02,4819.02 J1.3@3806,4863 3873,4930 4055.46,4930 4085.46,4900 5150.63,4900 5167.63,4917 5511.42,4917 5642.42,4786 5862.48,4786 5874.86,4798.38 6130.38,4798.38 6170,4838 6676.93,4838 6722.93,4792 7022.37,4792 7029.37,4785 7167,4785 7228,4846 7506,4846 7519,4833 v1(7519,4793)
  Bottom Layer w10: J5.7@741.56,3501.86 v7(798,3501.86) ; v7(966,3502) 966,3693.54 1097.46,3825 1261,3825 1269,3833 C55.1@1297,3833 1471.46,3833 1520.88,3783.57 U14.58@1550.85,3783.57
MISO_FPGA_: R156.2 U7.14 | length 4102.6
  Top Layer w7: U7.14@7216.09,4244.13 7234.87,4244.13 7260,4219 7260,4115 7322,4053 7357,4053
  Top Layer w10: v1(6904.44,888) 6926.02,888 6932.02,894 R156.2@6967.88,894 ; 7357,4053 7378,4053 7432,3999 v1(7432,3815)
  MidLayer2 w10: v1(6904.44,888) 7032.94,888 7083.94,837 7235,837 7285,887 7285,1171.88 7261.5,1195.38 7261.5,1834.44 7255.5,1840.44 7255.5,2121.5 7341,2207 7341,3001.29 7294.42,3047.88 7294.42,3316.89 7306,3328.47 7306,3518.47 7432,3644.47 v1(7432,3815)
MOSI_1_: C46.2 J2.29 U2.41 U6.28 U7.36 U14.31 U26.28 U31.14 U44.5 | length 17956
  Top Layer w7: v1(6884,4435) 6902.39,4416.61 6983.61,4416.61 7001.09,4434.09 U7.36@7010.39,4434.09
  Top Layer w10: U6.28@5152.77,2827.03 5153.74,2828 5289.39,2828 5328.92,2867.53 5328.92,3061.5 5281.42,3109 v4@5276.42,3109 ; v1(6498,4944) J2.29@6498,4864 6498,4832 6558,4772 6687.63,4772 6857,4602.63 6857,4462 v1(6884,4435) ; U26.28@6821.77,2386.79 6927.63,2386.79 6940.42,2374 7071.46,2374 7118.46,2421 7148.42,2421 v3(7180.42,2389) ; U2.41@7274.55,1606.4 7310.4,1606.4 7321,1617 7531.91,1617 7551.91,1597 7618,1597 v1(7644,1623)
  MidLayer2 w10: v1(2356,3364) 2407,3364 2488,3283 2488,3199.57 2487.5,3199.07 2487.5,3174.93 2488,3174.43 2488,3050.94 2480,3042.94 2480,2650.91 2553.78,2577.13 2553.78,2315.13 2472,2233.35 2472,2002.42 v3(2612.42,1862) ; v7@5101.38,4562.27 5081.31,4542.2 5081.31,4477.42 5210.42,4348.32 5210.42,3250.58 5276.42,3184.58 v4(5276.42,3114) v4@5276.42,3109 ; v1(7644,1623) 7677,1656 7677,2393 v7(7644,2426)
  MidLayer3 w10: v3(2612.42,1862) 2679.42,1795 2965.16,1795 2970.16,1790 7194,1790 7348.85,1635.15 7476.1,1635.15 7489.94,1649 7618,1649 v1(7644,1623) ; v7@5105,4576 5105,4605.53 5130.47,4631 5259.47,4631 5324.47,4696 5899.76,4696 5912.14,4708.38 6167.66,4708.38 6207.28,4748 6639.65,4748 6869.38,4518.26 6869.38,4449.62 v1(6884,4435) ; v4(5276.42,3114) 5330.57,3114 5343.57,3101 5369.54,3101 5561.54,3293 6270.91,3293 6320.91,3243 6729.21,3243 6945.21,3027 7051.42,3027 7073.92,3004.5 7073.92,2976.5 7021,2923.58 7021,2797 7180.42,2637.58 v3(7180.42,2389) 7328,2389 7376,2437 7633,2437 v7(7644,2426)
  Bottom Layer w10: U14.31@1991.8,3578.85 1991.8,3536.12 2038.5,3489.41 2038.5,3387.68 2008,3357.18 2008,3113 2066,3055 2157,3055 2208,3106 2208,3220 2232,3244 U44.5@2281.52,3244 2281.52,3335.52 2310,3364 v1(2356,3364) ; U31.14@2453.71,1773.39 2523.8,1773.39 v3(2612.42,1862) ; v1(6498,4944) 6511,4957 C46.2@6541.88,4957
  other v7: 5107,4573
MOSI_2_: C62.1 J1.2 J4.26 J5.3 U7.21 U14.46 | length 10932.2
  Top Layer w7: U7.21@7216.09,4354.37 7251.37,4354.37 7258.77,4361.77 7307.23,4361.77 v1(7316.23,4352.77)
  Top Layer w10: v1(798,3328.63) 817.37,3348 1453,3348 1479,3374 v1(1666,3374) ; J4.26@1233,5028 v8(1233,5125)
  MidLayer2 w10: v1(798,3328.63) 823.5,3354.13 823.5,4195.59 846,4218.09 846,4647.82 988,4789.82 988,5049 1046.44,5107.44 1179.44,5107.44 1197,5125 v8(1233,5125) ; v1(7316.23,4352.77) 7314.5,4354.5 7314.5,4594.5 7492,4772 v1(7492,4819)
  MidLayer3 w10: v8@1233,5127 v8(1233,5125) 1233,5102 1292.58,5042.42 1428.71,5042.42 1569.29,5183 3251,5183 3318,5116 3318,4835.77 3372.57,4781.2 3675.11,4781.2 3693.43,4799.52 3817.52,4799.52 3849,4831 3874,4831 J1.2@3906,4863 3955,4912 4048,4912 4078,4882 5158.09,4882 5175.09,4899 5503.96,4899 5634.96,4768 5869.94,4768 5882.32,4780.38 6137.84,4780.38 6177.46,4820 6669.47,4820 6715.47,4774 7014.91,4774 7021.91,4767 7174.46,4767 7226.46,4819 v1(7492,4819)
  Bottom Layer w10: J5.3@741.56,3328.63 v1(798,3328.63) ; v1(1666,3374) 1666,3495 1696.52,3525.52 U14.46@1696.52,3578.85 ; v1(7316.23,4352.77) 7316.23,4336.77 7334,4319 C62.1@7334,4299
MUX0_: R102.1 U7.20 U14.6 | length 6701.6
  Top Layer w7: U7.20@7216.09,4338.62 7283.62,4338.62 v1(7285,4337.24)
  MidLayer2 w10: v1(7154,4029) 7163,4020 7243,4020 7261,4038 7261,4313.24 v1(7285,4337.24)
  MidLayer3 w10: v1(2096,4014) 2140.46,4014 2241.65,4115.19 2241.65,4130.41 2256.59,4145.35 2271.81,4145.35 2490.46,4364 2767.63,4364 2929,4525.37 2929,4613.46 2952.54,4637 3286.74,4637 3304.74,4619 3744,4619 3762,4637 3885,4637 3917,4669 4520.37,4669 4574.37,4615 4681.37,4615 4904.37,4392 5228,4392 5388,4552 5959.41,4552 5971.79,4564.38 6227.31,4564.38 6266.93,4604 6580,4604 6693.73,4490.27 6693.73,4340.1 6803.32,4230.5 6812.39,4230.5 6890.89,4152 6937,4152 6940.5,4155.5 6940.5,4155.56 6955.44,4170.5 6955.5,4170.5 7030,4245 7192.76,4245 v1(7285,4337.24)
  Bottom Layer w10: v1(2096,4014) 2101.8,4019.8 U14.6@2157.15,4019.8 ; R102.1@7130,3988 7130,4005 v1(7154,4029)
MUX1_: R103.1 U7.1 U14.5 | length 6310
  Top Layer w7: v1@6938,4196 v1(6944,4196) 7010.29,4196 U7.1@7010.39,4195.91
  MidLayer3 w10: v1(2096.03,4051.97) 2152.97,4051.97 2223.65,4122.65 2223.65,4137.87 2249.13,4163.35 2264.35,4163.35 2483.5,4382.5 2760.68,4382.5 2911,4532.82 2911,4620.91 2945.28,4655.2 3294.93,4655.2 3312.93,4637.2 3735.65,4637.2 3753.98,4655.52 3877.17,4655.52 3908.65,4687 4527.82,4687 4581.82,4633 4688.82,4633 4911.82,4410 5220.14,4410 5380.14,4570 5951.95,4570 5964.33,4582.38 6219.85,4582.38 6259.47,4622 6587.46,4622 6711.73,4497.73 6711.73,4348.93 6812.16,4248.5 6819.84,4248.5 6898.34,4170 6918,4170 v1(6944,4196)
  Bottom Layer w10: v1(2096.03,4051.97) 2108.52,4039.48 U14.5@2157.15,4039.48 ; v1@6938,4196 6944,4190 6944,4163 6937,4156 6937,4029 6948,4018 7015,4018 7053,4056 7169,4056 7179.5,4045.5 7179.5,4008.5 7178,4007 R103.1@7178,3988.56
MUX2_: J2.35 R141.1 U7.30 U14.2 | length 7366.2
  Top Layer w7: U7.30@7104.87,4434.09 7104.87,4462.66 7108,4465.79 7108,4590.25 7123,4605.25 7123,4661 v1@7106,4678
  Top Layer w10: J2.35@6573,4864 6573,4833.91 6580.91,4826 6959,4826 v1(7099.35,4685.65)
  MidLayer2 w10: v1(7099.35,4685.65) 7125,4660 7125,4595 7226.5,4493.5 7226.5,4050.5 v1(7226,4050)
  MidLayer3 w10: v1@2611.75,4095.5 2605.5,4101.75 2605.5,4125.5 2980,4500 3028.46,4500 3111.07,4582.62 3264.21,4582.62 3282.21,4564.62 3766.53,4564.62 3784.53,4582.62 3907.53,4582.62 3939.53,4614.62 4498.38,4614.62 4552,4561 4659,4561 4882.38,4337.62 5250.53,4337.62 5410.91,4498 6033.53,4498 6113.53,4418 6447.46,4418 6569.46,4296 6661.46,4296 6780.96,4176.5 6790.02,4176.5 6883.52,4083 7193,4083 v1(7226,4050)
  Bottom Layer w10: U14.2@2157.15,4098.54 2195.54,4098.54 2254,4157 2497.94,4157 2564.94,4090 2586.06,4090 2591.56,4095.5 v1(2605.5,4095.5) ; R141.1@7226,3988.56 v1(7226,4050)
MUX3_: R142.1 U7.15 U14.1 | length 6108.5
  Top Layer w7: U7.15@7216.09,4259.88 7243.57,4259.88 7275,4228.45 7275,4141 v1(7295,4121)
  MidLayer3 w10: v1(2575.5,4115.5) 2575.5,4120.96 2972.54,4518 3021,4518 3103.62,4600.62 3271.67,4600.62 3289.67,4582.62 3759.07,4582.62 3777.07,4600.62 3900.07,4600.62 3932.07,4632.62 4505.84,4632.62 4559.46,4579 4666.46,4579 4889.84,4355.62 5243.07,4355.62 5403.46,4516 6040.99,4516 6120.99,4436 6454.91,4436 6576.91,4314 6668.91,4314 6788.41,4194.5 6797.47,4194.5 6890.97,4101 7193,4101 7210.5,4118.5 7292.5,4118.5 v1(7295,4121)
  Bottom Layer w10: U14.1@2157.15,4118.22 2189.22,4118.22 2246,4175 2516,4175 v1(2575.5,4115.5) ; R142.1@7274,3988.56 7274,4100 v1(7295,4121)
MUX_0: R92.2 R102.2 U2.1 | length 2524.2
  Top Layer w10: R92.2@7130,3926.44 v1(7130,3900) 7355.42,3674.58 7355.42,3266.27 7270.42,3181.27 7270.42,3006.63 7336.42,2940.63 7336.42,2315.45 7409.73,2242.13 7409.73,2138.11 7440.42,2107.43 7440.42,2063.88 7408.42,2031.88 7408.42,1992.12 7435.42,1965.12 7435.42,1898.17 7391.75,1854.5 7353.57,1854.5 7268.85,1769.78 U2.1@7248.96,1769.78
  Bottom Layer w10: v1(7130,3900) R102.2@7130,3932.88
MUX_1: R97.2 R103.2 U2.48 | length 2535.8
  Top Layer w10: R97.2@7178,3933.44 v1(7178,3900) 7178,3896 7182,3896 7178,3892 7178,3877.54 7373.42,3682.13 7373.42,3258.81 7288.42,3173.81 7288.42,3014.09 7354.42,2948.09 7354.42,2322.9 7427.73,2249.59 7427.73,2145.57 7458.42,2114.88 7458.42,2056.43 7426.42,2024.43 7426.42,1999.57 7453.42,1972.57 7453.42,1890.71 7399.2,1836.5 7361.02,1836.5 7274.55,1750.03 U2.48@7274.55,1744.19
  Bottom Layer w10: v1(7178,3900) R103.2@7178,3933.44
MUX_2: R99.2 R141.2 U2.47 | length 2539.4
  Top Layer w10: R99.2@7226,3933.44 v1(7226,3900.44) 7226,3855 7391.42,3689.58 7391.42,3251.35 7306.42,3166.35 7306.42,3021.54 7372.42,2955.54 7372.42,2330.36 7445.73,2257.04 7445.73,2153.02 7476.42,2122.34 7476.42,2042 7486.42,2032 7486.42,1898.26 7406.66,1818.5 7368.48,1818.5 7299.36,1749.39 7299.36,1733.89 7289.98,1724.51 U2.47@7274.55,1724.51
  Bottom Layer w10: v1(7226,3900.44) R141.2@7226,3933.44
MUX_3: R101.2 R142.2 U2.46 | length 2557.9
  Top Layer w10: R101.2@7274,3933.44 v1(7274,3900) 7274,3833 7409.42,3697.58 7409.42,3243.9 7324.42,3158.9 7324.42,3029 7390.42,2963 7390.42,2337.82 7463.73,2264.5 7463.73,2160.48 7494.42,2129.79 7494.42,2049.46 7504.42,2039.46 7504.42,1890.8 7414.11,1800.5 7375.93,1800.5 7317.36,1741.93 7317.36,1726.43 7295.75,1704.82 U2.46@7274.55,1704.82
  Bottom Layer w10: v1(7274,3900) R142.2@7274,3933.44
NCS_ADC_: R143.2 R144.2 U3.6 | length 163
  Top Layer w10: R144.2@6933.56,941 6933.98,941.42 R144.2@6933.98,947.42 ; R144.2@6933.56,947 R144.2@6933.98,947.42 ; R143.2@6933.98,989 R144.2@6933.98,947.42 ; R143.2@6933.98,995 6988,995 7010.58,972.42 U3.6@7038.84,972.42
NCS_ADC_FPGA_: R76.2 R144.1 | length 3403.2
  Top Layer w10: v1(6815,933) 6836.58,933 6844.58,941 R144.1@6878.44,941 ; v1(7381,3902.94) R76.2@7381,3932.44 R76.2@7381,3936.38
  MidLayer2 w10: v1(6815,933) 6815,944.52 6872,1001.52 6872,1251.12 6897,1276.12 6897,1353 7013,1469 7013,2137.54 7031,2155.54 7031,2597.46 6912,2716.46 6912,2905 7052,3045 7052,3171 7242,3361 7242,3545.02 7360.5,3663.52 7360.5,3844.62 7381,3865.12 v1(7381,3902.94)
NCS_AFE_: R285.2 U2.42 U14.90 | length 13767.9
  Top Layer w10: U2.42@7274.55,1626.08 7303.5,1626.08 7312.42,1635 7559,1635 7571,1623 v1(7605,1623)
  MidLayer2 w10: v8(2260,4248) 2241,4229 2241,4108.54 2423.04,3926.5 2450.56,3926.5 2545.5,3831.56 2545.5,3057.53 2516,3028.03 2516,2665.82 2589.78,2592.04 2589.78,2330.04 2681.25,2238.57 2668.42,2225.74 2668.42,1993.78 2678,1984.2 2678,1922.04 2660.42,1904.46 2660.42,1726.91 2603.42,1669.91 2603.42,1343.58 v11(2629,1318) ; v8(7544,3748) 7544,3661 7352,3469 7352,3309.42 7340.42,3297.84 7340.42,3066.93 7371.35,3036 7462,3036 7615.9,2882.1 7615.9,2644.9 7561,2590 7561,1633 7571,1623 v1(7605,1623)
  MidLayer3 w10: v7(1868,4108) 1971,4211 2117,4211 2182,4276 2232,4276 v8(2260,4248) ; v11(2629,1318) 2664,1353 2746.84,1353 2766.84,1333 5400.09,1333 5819.09,1752 6259.43,1752 6277,1734.43 6435.57,1734.43 6539,1631 6590,1631 6661.76,1559.24 7255.29,1559.24 7313.2,1617.15 7483.55,1617.15 7497.4,1631 7597,1631 v1(7605,1623)
  Bottom Layer w10: v7(1868,4108) 1893.37,4133.37 U14.90@1893.37,4185.15 ; R285.2@6481,4735.88 6481,4713 6493,4701 6685.54,4701 6785,4601.54 6785,4154 6733,4102 6733,3999.91 6770,3962.91 6770,3925 6794.09,3900.91 6835,3900.91 6987.91,3748 v8(7544,3748)
NCS_BOTSTACK_: R254.2 U6.30 U14.16 | length 5992
  Top Layer w10: U6.30@5152.77,2866.4 5276.88,2866.4 5292.92,2882.44 5292.92,2966.08 5276.42,2982.58 v4@5276.42,3011
  MidLayer2 w10: v4@5276.42,3011 5363,3011 5386,3034 5386,3164 5246.42,3303.58 5246.42,3929 v11(5323.42,4006)
  MidLayer3 w10: v8@2558,3893.94 v8(2558,3900) 2570,3912 2632,3912 2711,3833 4110,3833 4238,3961 4647,3961 4702,4016 5313.42,4016 v11(5323.42,4006) 5413,4006 v1(5596,4189)
  Bottom Layer w10: U14.16@2157.15,3822.94 2194.51,3822.94 2218.19,3799.27 2375.71,3799.27 2377.44,3801 2426,3801 2525,3900 v8(2558,3900) ; v1(5596,4189) 5621.5,4214.5 5735.5,4214.5 6145,4624 R254.2@6145,4733.88
  other v4: 5276.42,3020
NCS_CELLV_: R143.1 U7.17 U14.59 | length 10836.3
  Top Layer w7: U7.17@7216.09,4291.38 7254.5,4291.38 7304.88,4241 7305,4241 7305,4168 7329,4144 7403.06,4144 7432.06,4173 7451.94,4173 7475,4149.94 v1(7475,4148)
  Top Layer w10: v1(6815.42,981) 6837,981 6845,989 R143.1@6878.86,989
  MidLayer2 w10: v1(6815.42,981) 6817.84,981 6854,1017.16 6854,1260.57 6879,1285.57 6879,1360.46 6995,1476.46 6995,2145 7013,2163 7013,2590 6894,2709 6894,2912.46 7034,3052.46 7034,3178.46 7143.14,3287.6 7143.14,3351.13 7224,3431.99 7224,3552.48 7300.5,3628.98 7300.5,3971.44 7475,4145.94 v1(7475,4148)
  MidLayer3 w10: v7(1676,3844) 1701.5,3818.5 1726.56,3818.5 1757.06,3849 1870.54,3849 1917.54,3896 2086.46,3896 2101.46,3881 2229,3881 2278,3930 2610,3930 2635,3955 2635,4129.54 2987.46,4482 3035.91,4482 3073.41,4519.5 3137.5,4519.5 3182.62,4564.62 3256.76,4564.62 3274.76,4546.62 3773.98,4546.62 3791.98,4564.62 3914.98,4564.62 3946.98,4596.62 4490.38,4596.62 4544,4543 4651.54,4543 4874.93,4319.62 5257.98,4319.62 5418.37,4480 6026.08,4480 6106.08,4400 6440,4400 6562,4278 6654,4278 6773.5,4158.5 6782.56,4158.5 6921.06,4020 7117,4020 7133.5,4003.5 7332.56,4003.5 7475,4145.94 v1(7475,4148)
  Bottom Layer w10: U14.59@1550.85,3803.26 1635.26,3803.26 v7(1676,3844)
NCS_FLASH: U14.92 U44.1 | length 1756.5
  Top Layer w10: v7(2210,4248) 2184.5,4222.5 2184.5,3634.5 2248,3571 2248,3404 v1(2235,3391)
  MidLayer3 w10: v7(1917,4107) 1917,4131.54 1978.46,4193 2124.46,4193 2179.46,4248 v7(2210,4248)
  Bottom Layer w10: v7(1917,4107) 1932.74,4122.74 U14.92@1932.74,4185.15 ; U44.1@2096.48,3094 2167,3094 2190,3117 2190,3365 2216,3391 v1(2235,3391)
NCS_FPGA_: J2.33 U7.31 U14.29 | length 7249.2
  Top Layer w7: U7.31@7089.13,4434.09 7089.13,4468.13 7093,4472 7093,4596.5 7099,4602.5 v1(7099,4639)
  Top Layer w10: J2.33@6548,4864 6548,4833.46 6573.46,4808 6930,4808 v1(7099,4639)
  MidLayer2 w10: v1(2006,3723) 2006,3887.94 2131,4012.94 2131,4510 v8(2167,4546)
  MidLayer3 w10: v8(2167,4546) 2209.5,4588.5 2631.44,4588.5 2701.94,4518 2760.06,4518 2780,4537.94 2780,4642.65 2900.55,4763.2 3339.66,4763.2 3357.66,4745.2 3690.02,4745.2 3708.34,4763.52 3832.43,4763.52 3863.91,4795 4450.46,4795 4501.46,4846 5173,4846 5190,4863 5489.05,4863 5620.05,4732 5884.85,4732 5897.23,4744.38 6152.75,4744.38 6192.37,4784 6654.56,4784 6700.56,4738 7000,4738 v1(7099,4639)
  Bottom Layer w10: v1(2006,3723) 2031.17,3697.83 U14.29@2031.17,3578.85
NCS_TOPSTACK_: R253.2 U14.17 U26.30 | length 8313.9
  Top Layer w10: U26.30@6821.77,2426.16 6969.15,2426.16 7026.99,2484 7026.99,2523.99 7192,2689 7192,2881.4 7125.14,2948.26 7125.14,3365.27 7211.42,3451.54 7211.42,3597.58 v4(7133,3676)
  MidLayer2 w10: v1(5974,4824) 5960,4810 5960,4547 6108,4399 v11(6108,3795)
  MidLayer3 w10: v8(2606,3772) 2616,3782 2634.18,3782 2673.18,3743 4360.84,3743 4371.84,3754 4432.84,3754 4549.84,3871 4971.3,3871 5047.3,3795 v11(6108,3795) 6260.82,3795 6280.82,3815 6502.27,3815 6515.41,3828.15 6555.15,3828.15 6627,3900 6747,3900 6851.42,3795.58 6851.42,3603.54 6897.96,3557 6966.42,3557 7085.42,3676 v4(7133,3676)
  Bottom Layer w10: U14.17@2157.15,3803.26 2188.74,3803.26 2210.73,3781.27 2537.73,3781.27 2547,3772 v8(2606,3772) ; v1(5974,4824) 5974,4771 6011.12,4733.88 R253.2@6097,4733.88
